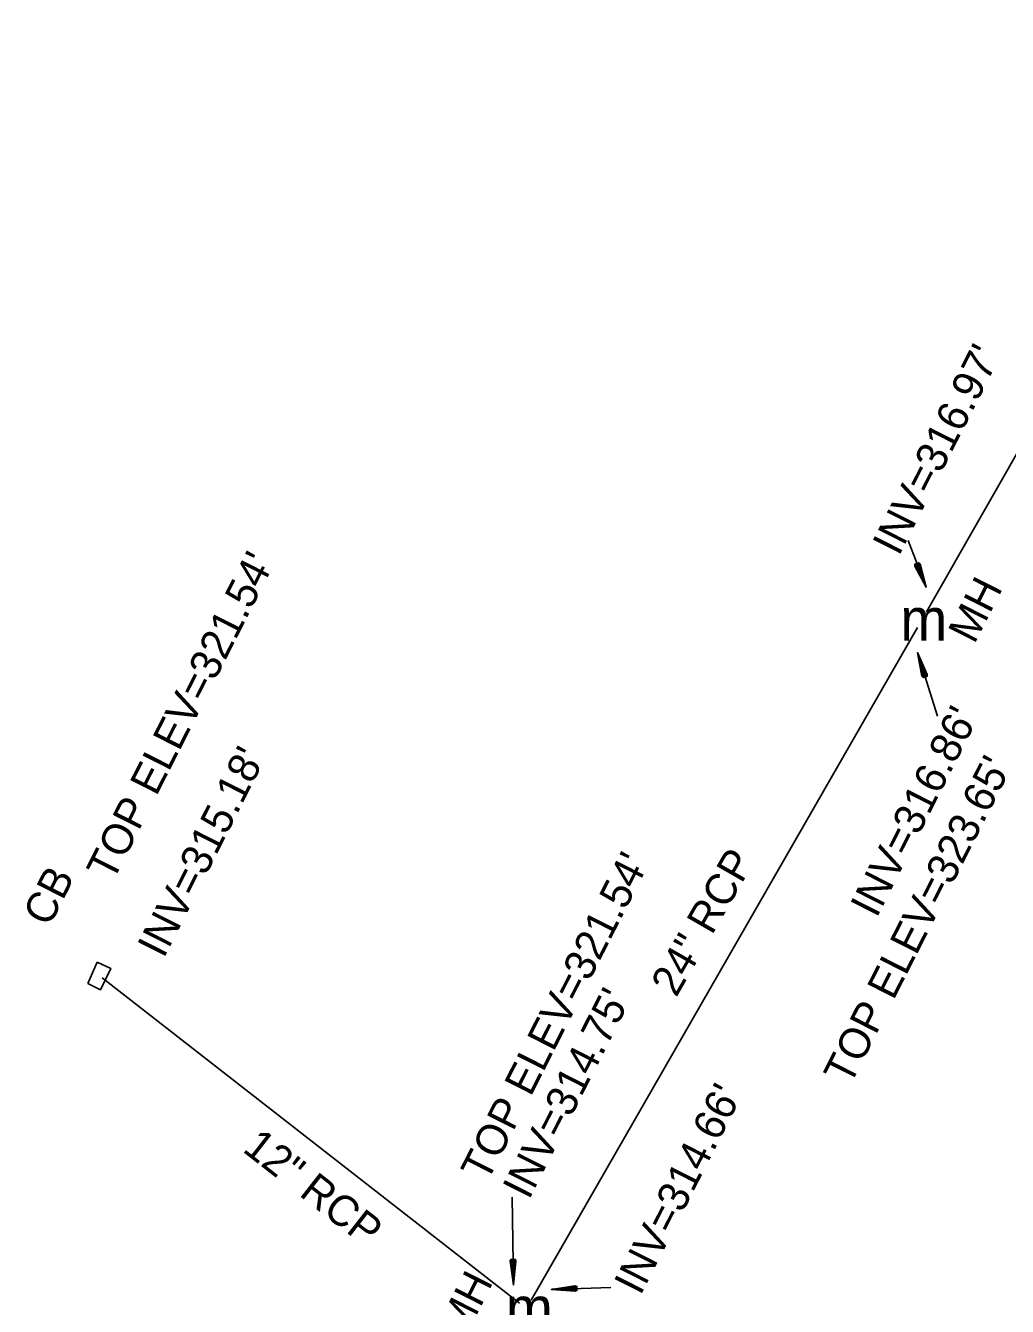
# Model space of a CAD drawing. Extents: x 1975859 to 1978323, y 778892 to 782836.
# Drawn here: x 1978078.9 to 1978206.4, y 782622.9 to 782789.4 of the extents above; entities that cross this region are included whole.
import ezdxf

# ---------------------------------------------------------------- set-up
doc = ezdxf.new("R2010")
doc.units = 0
for name, color, linetype in [('Exist Structure Minor Catch Basin', 7, 'Continuous'), ('Exist Structure Minor Catch Basin Text', 7, 'Continuous'), ('Exist Structure Minor Catch Basin Top Elevation', 7, 'Continuous'), ('Exist Structure Minor Pipes RCP 12 Inch', 7, 'Continuous'), ('Exist Structure Minor Pipes RCP 12 Inch Text', 7, 'Continuous'), ('Exist Structure Minor Pipes RCP 15 Inch Invert', 7, 'Continuous'), ('Exist Structure Minor Pipes RCP 24 Inch', 7, 'Continuous'), ('Exist Structure Minor Pipes RCP 24 Inch Invert', 7, 'Continuous'), ('Exist Structure Minor Pipes RCP 24 Inch Text', 7, 'Continuous'), ('Exist Structure Minor Storm Sewer Manhole CELL', 7, 'Continuous'), ('Exist Structure Minor Storm Sewer Manhole Text', 7, 'Continuous'), ('Exist Structure Minor Storm Sewer Manhole Top Elevation', 7, 'Continuous')]:
    doc.layers.add(name, color=color, linetype=linetype)

msp = doc.modelspace()

# ---------------------------------------------------------------- linework, layer by layer
at = {"layer": 'Exist Structure Minor Catch Basin'}
msp.add_line((1978088.18, 782667.63), (1978086.94, 782664.86), dxfattribs=at)
msp.add_lwpolyline([(1978088.18, 782667.63), (1978089.92, 782666.82), (1978088.58, 782664.05), (1978086.94, 782664.86)], dxfattribs=at)
at = {"layer": 'Exist Structure Minor Pipes RCP 12 Inch'}
msp.add_line((1978143.03, 782623.29), (1978088.82, 782665.59), dxfattribs=at)
at = {"layer": 'Exist Structure Minor Pipes RCP 15 Inch Invert'}
for p, q in [((1978142.11, 782637.08), (1978142.25, 782625.68)), ((1978141.94, 782628.99), (1978142.47, 782629)), ((1978142.21, 782628.68), (1978141.99, 782628.95)), ((1978142.21, 782628.68), (1978142.04, 782629)), ((1978142.21, 782628.68), (1978142.15, 782629)), ((1978142.21, 782628.68), (1978142.26, 782629)), ((1978142.21, 782628.68), (1978142.35, 782629)), ((1978142.42, 782628.95), (1978142.21, 782628.68))]:
    msp.add_line(p, q, dxfattribs=at)
for points in [[(1978141.94, 782628.99), (1978141.85, 782628.76), (1978142.25, 782625.68), (1978142.57, 782628.77), (1978142.47, 782629)], [(1978142.52, 782628.89), (1978142.25, 782625.68), (1978141.89, 782628.88)], [(1978142, 782628.84), (1978142.25, 782625.68), (1978141.94, 782628.99), (1978141.99, 782628.95), (1978142, 782628.84), (1978142.21, 782628.68), (1978142.42, 782628.85), (1978142.42, 782628.95), (1978142.47, 782629), (1978142.25, 782625.68), (1978142.42, 782628.85)], [(1978142.25, 782625.86), (1978142.25, 782625.78), (1978142.23, 782625.87), (1978142.22, 782625.96), (1978142.24, 782625.87), (1978142.26, 782625.95), (1978142.27, 782626.04), (1978142.24, 782625.96), (1978142.22, 782626.06), (1978142.21, 782626.15), (1978142.24, 782626.06), (1978142.27, 782626.14), (1978142.28, 782626.23), (1978142.24, 782626.15), (1978142.2, 782626.24), (1978142.2, 782626.34), (1978142.24, 782626.24), (1978142.28, 782626.32), (1978142.29, 782626.42), (1978142.24, 782626.34), (1978142.19, 782626.43), (1978142.18, 782626.52), (1978142.24, 782626.43), (1978142.29, 782626.51), (1978142.3, 782626.6), (1978142.24, 782626.52), (1978142.17, 782626.61), (1978142.17, 782626.71), (1978142.23, 782626.62), (1978142.3, 782626.7), (1978142.31, 782626.79), (1978142.23, 782626.71), (1978142.16, 782626.8), (1978142.15, 782626.9), (1978142.23, 782626.81), (1978142.31, 782626.88), (1978142.32, 782626.98), (1978142.23, 782626.9), (1978142.14, 782626.99), (1978142.14, 782627.08), (1978142.23, 782626.99), (1978142.32, 782627.07), (1978142.33, 782627.16), (1978142.23, 782627.09), (1978142.13, 782627.18), (1978142.12, 782627.27), (1978142.23, 782627.18), (1978142.33, 782627.26), (1978142.34, 782627.35), (1978142.23, 782627.27), (1978142.12, 782627.36), (1978142.11, 782627.46), (1978142.23, 782627.37), (1978142.34, 782627.44), (1978142.35, 782627.54), (1978142.22, 782627.46), (1978142.1, 782627.55), (1978142.09, 782627.64), (1978142.22, 782627.55), (1978142.35, 782627.63), (1978142.36, 782627.73), (1978142.22, 782627.65), (1978142.09, 782627.74), (1978142.08, 782627.83), (1978142.22, 782627.74), (1978142.36, 782627.82), (1978142.37, 782627.91), (1978142.22, 782627.83), (1978142.07, 782627.92), (1978142.06, 782628.02), (1978142.21, 782627.93), (1978142.37, 782628.01), (1978142.38, 782628.1), (1978142.22, 782628.02), (1978142.06, 782628.11), (1978142.05, 782628.2), (1978142.22, 782628.12), (1978142.38, 782628.19), (1978142.39, 782628.29), (1978142.22, 782628.21), (1978142.04, 782628.3), (1978142.04, 782628.39), (1978142.21, 782628.3), (1978142.39, 782628.38), (1978142.4, 782628.47), (1978142.21, 782628.4), (1978142.03, 782628.48), (1978142.02, 782628.58), (1978142.21, 782628.49), (1978142.4, 782628.57), (1978142.41, 782628.66), (1978142.21, 782628.58), (1978142.01, 782628.67), (1978142.01, 782628.76), (1978142.21, 782628.68), (1978142.41, 782628.75)]]:
    msp.add_lwpolyline(points, dxfattribs=at)
at = {"layer": 'Exist Structure Minor Pipes RCP 24 Inch'}
for p, q in [((1978239.29, 782789.4), (1978195.95, 782713.16)), ((1978194.77, 782711.15), (1978144.56, 782623.71))]:
    msp.add_line(p, q, dxfattribs=at)
at = {"layer": 'Exist Structure Minor Pipes RCP 24 Inch Invert'}
for p, q in [((1978195.88, 782716.38), (1978193.54, 782722.44)), ((1978194.44, 782719.38), (1978194.94, 782719.57)), ((1978194.8, 782719.18), (1978194.82, 782719.53)), ((1978194.8, 782719.18), (1978194.5, 782719.36)), ((1978194.8, 782719.18), (1978194.53, 782719.42)), ((1978194.8, 782719.18), (1978194.63, 782719.46)), ((1978194.8, 782719.18), (1978194.74, 782719.5)), ((1978194.91, 782719.51), (1978194.8, 782719.18)), ((1978194.78, 782707.88), (1978197.35, 782699.61)), ((1978196.02, 782704.79), (1978195.51, 782704.64)), ((1978195.54, 782704.69), (1978195.67, 782705.02)), ((1978195.67, 782705.02), (1978195.62, 782704.67)), ((1978195.67, 782705.02), (1978195.96, 782704.82)), ((1978195.67, 782705.02), (1978195.92, 782704.76)), ((1978195.67, 782705.02), (1978195.82, 782704.73)), ((1978195.67, 782705.02), (1978195.71, 782704.69)), ((1978154.92, 782625.35), (1978147.19, 782625.09)), ((1978150.18, 782625.19), (1978150.45, 782625.42)), ((1978150.18, 782625.19), (1978150.5, 782625.37)), ((1978150.18, 782625.19), (1978150.5, 782625.26)), ((1978150.46, 782624.98), (1978150.18, 782625.19)), ((1978150.18, 782625.19), (1978150.51, 782625.15)), ((1978150.18, 782625.19), (1978150.51, 782625.06)), ((1978150.49, 782625.47), (1978150.51, 782624.94))]:
    msp.add_line(p, q, dxfattribs=at)
for points in [[(1978194.44, 782719.38), (1978194.43, 782719.13), (1978195.88, 782716.38), (1978195.1, 782719.39), (1978194.94, 782719.57)], [(1978194.55, 782719.26), (1978195.88, 782716.38), (1978194.44, 782719.38), (1978194.5, 782719.36), (1978194.55, 782719.26), (1978194.8, 782719.18), (1978194.94, 782719.41), (1978194.91, 782719.51), (1978194.94, 782719.57), (1978195.88, 782716.38), (1978194.94, 782719.41)], [(1978195.02, 782719.48), (1978195.88, 782716.38), (1978194.44, 782719.26)], [(1978195.83, 782716.55), (1978195.84, 782716.47), (1978195.8, 782716.55), (1978195.76, 782716.64), (1978195.81, 782716.56), (1978195.8, 782716.64), (1978195.77, 782716.73), (1978195.78, 782716.65), (1978195.72, 782716.72), (1978195.68, 782716.81), (1978195.74, 782716.73), (1978195.74, 782716.82), (1978195.72, 782716.91), (1978195.71, 782716.82), (1978195.64, 782716.89), (1978195.6, 782716.98), (1978195.68, 782716.91), (1978195.69, 782717), (1978195.66, 782717.08), (1978195.64, 782716.99), (1978195.56, 782717.06), (1978195.53, 782717.15), (1978195.61, 782717.08), (1978195.63, 782717.17), (1978195.6, 782717.26), (1978195.58, 782717.17), (1978195.49, 782717.23), (1978195.45, 782717.32), (1978195.54, 782717.26), (1978195.58, 782717.35), (1978195.55, 782717.44), (1978195.51, 782717.34), (1978195.41, 782717.4), (1978195.37, 782717.49), (1978195.47, 782717.43), (1978195.52, 782717.53), (1978195.49, 782717.62), (1978195.44, 782717.52), (1978195.33, 782717.57), (1978195.29, 782717.66), (1978195.41, 782717.61), (1978195.47, 782717.71), (1978195.44, 782717.8), (1978195.37, 782717.69), (1978195.25, 782717.74), (1978195.21, 782717.83), (1978195.34, 782717.78), (1978195.41, 782717.89), (1978195.38, 782717.98), (1978195.31, 782717.87), (1978195.17, 782717.91), (1978195.13, 782718), (1978195.27, 782717.95), (1978195.35, 782718.07), (1978195.33, 782718.16), (1978195.24, 782718.04), (1978195.09, 782718.08), (1978195.05, 782718.17), (1978195.21, 782718.13), (1978195.3, 782718.25), (1978195.27, 782718.34), (1978195.17, 782718.22), (1978195.01, 782718.25), (1978194.97, 782718.34), (1978195.14, 782718.3), (1978195.24, 782718.43), (1978195.22, 782718.52), (1978195.1, 782718.39), (1978194.94, 782718.42), (1978194.9, 782718.51), (1978195.06, 782718.48), (1978195.19, 782718.6), (1978195.16, 782718.69), (1978195.04, 782718.57), (1978194.86, 782718.59), (1978194.82, 782718.68), (1978195, 782718.65), (1978195.13, 782718.78), (1978195.1, 782718.87), (1978194.97, 782718.74), (1978194.78, 782718.76), (1978194.74, 782718.85), (1978194.94, 782718.83), (1978195.08, 782718.96), (1978195.05, 782719.05), (1978194.9, 782718.92), (1978194.7, 782718.93), (1978194.66, 782719.02), (1978194.87, 782719), (1978195.02, 782719.14), (1978194.99, 782719.23), (1978194.83, 782719.09), (1978194.62, 782719.1), (1978194.58, 782719.19), (1978194.8, 782719.18), (1978194.97, 782719.32)], [(1978195.92, 782704.92), (1978194.78, 782707.88), (1978196.02, 782704.79), (1978195.96, 782704.82), (1978195.92, 782704.92), (1978195.67, 782705.02), (1978195.52, 782704.8), (1978195.54, 782704.69), (1978195.51, 782704.64), (1978194.78, 782707.88), (1978195.52, 782704.8)], [(1978196.02, 782704.79), (1978196.04, 782705.04), (1978194.78, 782707.88), (1978195.35, 782704.83), (1978195.51, 782704.64)], [(1978195.43, 782704.73), (1978194.78, 782707.88), (1978196.03, 782704.92)], [(1978194.82, 782707.71), (1978194.81, 782707.79), (1978194.85, 782707.71), (1978194.88, 782707.62), (1978194.84, 782707.7), (1978194.84, 782707.62), (1978194.87, 782707.53), (1978194.86, 782707.61), (1978194.92, 782707.53), (1978194.95, 782707.44), (1978194.89, 782707.52), (1978194.89, 782707.44), (1978194.91, 782707.35), (1978194.92, 782707.43), (1978194.98, 782707.36), (1978195.02, 782707.27), (1978194.95, 782707.34), (1978194.93, 782707.26), (1978194.95, 782707.17), (1978194.98, 782707.26), (1978195.05, 782707.18), (1978195.08, 782707.09), (1978195, 782707.17), (1978194.97, 782707.08), (1978195, 782706.98), (1978195.03, 782707.08), (1978195.12, 782707.01), (1978195.15, 782706.92), (1978195.06, 782706.99), (1978195.02, 782706.89), (1978195.04, 782706.8), (1978195.09, 782706.9), (1978195.18, 782706.83), (1978195.22, 782706.74), (1978195.11, 782706.81), (1978195.06, 782706.71), (1978195.08, 782706.62), (1978195.14, 782706.72), (1978195.25, 782706.66), (1978195.28, 782706.57), (1978195.17, 782706.63), (1978195.1, 782706.53), (1978195.13, 782706.44), (1978195.2, 782706.54), (1978195.32, 782706.48), (1978195.35, 782706.4), (1978195.23, 782706.45), (1978195.15, 782706.35), (1978195.17, 782706.26), (1978195.25, 782706.36), (1978195.39, 782706.31), (1978195.42, 782706.22), (1978195.28, 782706.27), (1978195.19, 782706.16), (1978195.21, 782706.07), (1978195.31, 782706.18), (1978195.45, 782706.13), (1978195.49, 782706.05), (1978195.34, 782706.09), (1978195.23, 782705.98), (1978195.26, 782705.89), (1978195.36, 782706), (1978195.52, 782705.96), (1978195.55, 782705.87), (1978195.39, 782705.91), (1978195.28, 782705.8), (1978195.3, 782705.71), (1978195.42, 782705.82), (1978195.59, 782705.78), (1978195.62, 782705.7), (1978195.46, 782705.74), (1978195.32, 782705.62), (1978195.34, 782705.53), (1978195.48, 782705.65), (1978195.65, 782705.61), (1978195.69, 782705.52), (1978195.5, 782705.56), (1978195.36, 782705.44), (1978195.39, 782705.34), (1978195.53, 782705.47), (1978195.72, 782705.43), (1978195.75, 782705.35), (1978195.56, 782705.38), (1978195.41, 782705.25), (1978195.43, 782705.16), (1978195.59, 782705.29), (1978195.79, 782705.26), (1978195.82, 782705.17), (1978195.61, 782705.2), (1978195.45, 782705.07), (1978195.47, 782704.98), (1978195.64, 782705.11), (1978195.85, 782705.08), (1978195.89, 782705), (1978195.67, 782705.02), (1978195.5, 782704.89)], [(1978150.49, 782625.47), (1978150.26, 782625.55), (1978147.19, 782625.09), (1978150.28, 782624.84), (1978150.51, 782624.94)], [(1978150.4, 782624.89), (1978147.19, 782625.09), (1978150.38, 782625.51)], [(1978150.34, 782625.41), (1978147.19, 782625.09), (1978150.49, 782625.47), (1978150.45, 782625.42), (1978150.34, 782625.41), (1978150.18, 782625.19), (1978150.36, 782624.99), (1978150.46, 782624.98), (1978150.51, 782624.94), (1978147.19, 782625.09), (1978150.36, 782624.99)], [(1978147.36, 782625.09), (1978147.28, 782625.1), (1978147.37, 782625.11), (1978147.47, 782625.12), (1978147.38, 782625.1), (1978147.45, 782625.08), (1978147.55, 782625.08), (1978147.47, 782625.1), (1978147.56, 782625.13), (1978147.65, 782625.14), (1978147.56, 782625.11), (1978147.64, 782625.08), (1978147.74, 782625.08), (1978147.66, 782625.11), (1978147.75, 782625.15), (1978147.84, 782625.16), (1978147.75, 782625.11), (1978147.83, 782625.07), (1978147.92, 782625.07), (1978147.84, 782625.12), (1978147.93, 782625.17), (1978148.03, 782625.18), (1978147.94, 782625.12), (1978148.02, 782625.07), (1978148.11, 782625.06), (1978148.03, 782625.12), (1978148.12, 782625.19), (1978148.21, 782625.19), (1978148.12, 782625.12), (1978148.2, 782625.06), (1978148.3, 782625.06), (1978148.22, 782625.13), (1978148.31, 782625.2), (1978148.4, 782625.21), (1978148.31, 782625.13), (1978148.39, 782625.05), (1978148.48, 782625.05), (1978148.4, 782625.13), (1978148.49, 782625.22), (1978148.58, 782625.23), (1978148.5, 782625.14), (1978148.58, 782625.05), (1978148.67, 782625.04), (1978148.59, 782625.14), (1978148.68, 782625.24), (1978148.77, 782625.25), (1978148.69, 782625.14), (1978148.77, 782625.04), (1978148.86, 782625.04), (1978148.78, 782625.15), (1978148.86, 782625.26), (1978148.96, 782625.27), (1978148.87, 782625.15), (1978148.95, 782625.04), (1978149.05, 782625.03), (1978148.97, 782625.15), (1978149.05, 782625.28), (1978149.14, 782625.29), (1978149.06, 782625.16), (1978149.14, 782625.03), (1978149.23, 782625.03), (1978149.15, 782625.16), (1978149.24, 782625.3), (1978149.33, 782625.31), (1978149.25, 782625.16), (1978149.33, 782625.02), (1978149.42, 782625.02), (1978149.34, 782625.17), (1978149.42, 782625.31), (1978149.52, 782625.32), (1978149.43, 782625.18), (1978149.51, 782625.02), (1978149.61, 782625.01), (1978149.53, 782625.17), (1978149.61, 782625.33), (1978149.7, 782625.34), (1978149.62, 782625.17), (1978149.7, 782625.01), (1978149.79, 782625.01), (1978149.71, 782625.18), (1978149.8, 782625.35), (1978149.89, 782625.36), (1978149.81, 782625.18), (1978149.89, 782625), (1978149.98, 782625), (1978149.9, 782625.18), (1978149.98, 782625.37), (1978150.08, 782625.38), (1978150, 782625.19), (1978150.07, 782625), (1978150.17, 782624.99), (1978150.09, 782625.19), (1978150.17, 782625.39), (1978150.26, 782625.4), (1978150.18, 782625.19), (1978150.26, 782624.99)]]:
    msp.add_lwpolyline(points, dxfattribs=at)

# ---------------------------------------------------------------- texts
at = {"layer": 'Exist Structure Minor Catch Basin Text'}
msp.add_text('CB', height=4, rotation=63.1198, dxfattribs=at).set_placement((1978081.94, 782672.1))
at = {"layer": 'Exist Structure Minor Catch Basin Top Elevation'}
for p in [(1978090.2, 782677.97), (1978138.85, 782638.9)]:
    msp.add_text("TOP ELEV=321.54'", height=4, rotation=63.1198, dxfattribs=at).set_placement(p)
at = {"layer": 'Exist Structure Minor Pipes RCP 12 Inch Text'}
msp.add_text('12" RCP', height=4, rotation=322.0363, dxfattribs=at).set_placement((1978106.91, 782643.11))
at = {"layer": 'Exist Structure Minor Pipes RCP 15 Inch Invert'}
for s, p in [("INV=315.18'", (1978096.81, 782668)), ("INV=314.75'", (1978144.27, 782636.61))]:
    msp.add_text(s, height=4, rotation=63.1198, dxfattribs=at).set_placement(p)
at = {"layer": 'Exist Structure Minor Pipes RCP 24 Inch Invert'}
for s, p in [("INV=316.97'", (1978192.34, 782720.32)), ("INV=316.86'", (1978189.45, 782673.26)), ("INV=314.66'", (1978158.76, 782624.18))]:
    msp.add_text(s, height=4, rotation=63.1198, dxfattribs=at).set_placement(p)
at = {"layer": 'Exist Structure Minor Pipes RCP 24 Inch Text'}
msp.add_text('24" RCP', height=4, rotation=60.1376, dxfattribs=at).set_placement((1978163.41, 782662.95))
at = {"layer": 'Exist Structure Minor Storm Sewer Manhole CELL'}
for p in [(1978192.53, 782709.44), (1978141.27, 782619.91)]:
    msp.add_text('m', height=5.5, dxfattribs=at).set_placement(p)
at = {"layer": 'Exist Structure Minor Storm Sewer Manhole Text'}
for p in [(1978202.16, 782708.88), (1978135.93, 782618.65)]:
    msp.add_text('MH', height=4, rotation=63.1198, dxfattribs=at).set_placement(p)
at = {"layer": 'Exist Structure Minor Storm Sewer Manhole Top Elevation'}
msp.add_text("TOP ELEV=323.65'", height=4, rotation=63.1198, dxfattribs=at).set_placement((1978185.99, 782651.43))

doc.saveas('drawing.dxf')
